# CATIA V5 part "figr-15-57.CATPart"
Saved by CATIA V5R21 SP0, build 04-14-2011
Part number: Part1
Bounding box of the stored display mesh (mm): x -92.936 to 49.742, y -31.904 to 31.904, z 0 to 63.808
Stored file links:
  D:\CATIA V5R21 E-RESOURCES\CATIA-V5R21\catia-v5r21-prt\c15-catia-v5r20-prt\c15-catia-v5r21-figr-15-57.CATPart
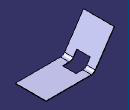
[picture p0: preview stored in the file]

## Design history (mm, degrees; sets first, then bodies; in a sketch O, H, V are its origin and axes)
SheetMetalParameters1: Thickness 1, BendRadius 10, KFactor 0.5 {= log(min(100,max(20*SheetMetalParameters1.BendRadius,SheetMetalParameters1.Thickness)/SheetMetalParameters1.Thickness))/log(100)/2}, ReliefRadialLength 1, ReliefAxialLength 2, MinimumBendRadius 0
Body1 (main body)
  Sketch1 on xy-plane, origin (0, 0, 0), H (1, 0, 0), V (0, 1, 0)
    line L1 (49.7419, 31.9042) -> (49.7419, -31.9042)
    line L2 (49.7419, -31.9042) -> (-49.7419, -31.9042)
    line L3 (-49.7419, -31.9042) -> (-49.7419, 31.9042)
    line L4 (-49.7419, 31.9042) -> (49.7419, 31.9042)
    vertical: L1 V, L3 V
    horizontal: L2 H, L4 H
    equidistance: L1 L3 O, L2 L4 O
  Wall1: Thickness 1, Profile Sketch1
  d_NewWallOnEdge1: NewWallOnEdge_Edge edge [face of Wall1 | face of Wall1], NewWallOnEdge_Length 63.8083, NewWallOnEdge_HeightLimitOffset 0, NewWallOnEdge_WidthOffset1 0, NewWallOnEdge_WidthOffset2 0, NewWallOnEdge_Angle 124, NewWallOnEdge_BendRadiusValue 10 {= SheetMetalParameters1.BendRadius}, NewWallOnEdge_BendTable SheetMetalParameters1, KFacteur 0.5 {= log(min(100,max(20*d_NewWallOnEdge1.Radius,SheetMetalParameters1.Thickness)/SheetMetalParameters1.Thickness))/log(100)/2}
  Sketch2 on face of d_NewWallOnEdge1, origin (0, 0, 1), H (1, 0, 0), V (0, 1, 0)
    point P1 (-49.1841, 0)
    line L1 (-30.5497, 14.1437) -> (-30.5497, -14.1437)
    line L2 (-30.5497, -14.1437) -> (-67.8185, -14.1437)
    line L3 (-67.8185, -14.1437) -> (-67.8185, 14.1437)
    line L4 (-67.8185, 14.1437) -> (-30.5497, 14.1437)
    coincidence: P1 H
    vertical: L1 V, L3 V
    horizontal: L2 H, L4 H
    equidistance: L1 L3 P1, L2 L4 P1
  CutOut1: Direction Sketch2, EndLimit through (limit type 2), Orientation true, Profile Sketch2, StartLimit through (limit type 2)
